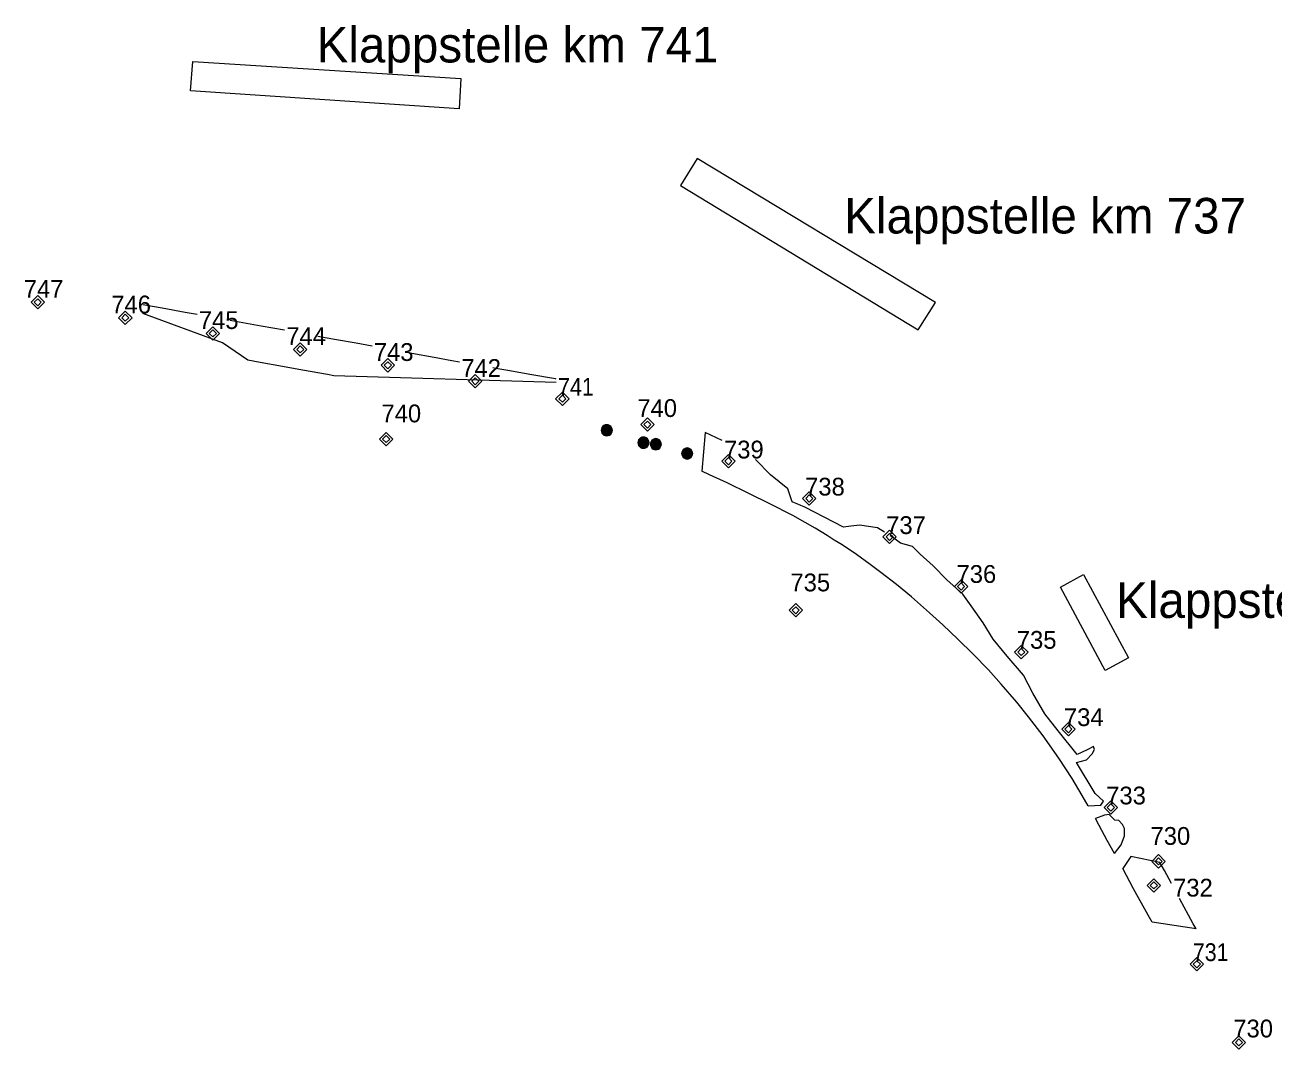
# Model space of a CAD drawing. Extents: x 3461750 to 3585707, y 5917729 to 5985917.
# Drawn here: x 3466140 to 3480178, y 5974405 to 5985917 of the extents above; entities that cross this region are included whole.
import ezdxf

# ---------------------------------------------------------------- set-up
doc = ezdxf.new("R2010")
doc.units = 0
doc.header["$LTSCALE"] = 80
doc.layers.add('11', color=7, linetype='Continuous')
for name, color, linetype, lineweight in [('12', 7, 'Continuous', 13), ('13', 7, 'Continuous', 13), ('14', 7, 'Continuous', 13), ('15', 7, 'Continuous', 13), ('2', 7, 'Continuous', 13), ('3', 7, 'Continuous', 13), ('6', 7, 'Continuous', 13)]:
    doc.layers.add(name, color=color, linetype=linetype, lineweight=lineweight)

msp = doc.modelspace()

# ---------------------------------------------------------------- hatches: boundary and pattern name
at = {"layer": '3'}
for points in [[(3472747.11, 5981360.51), (3472744.18, 5981377.13), (3472737.93, 5981392.23), (3472727.99, 5981405.19), (3472715.03, 5981415.13), (3472699.94, 5981421.38), (3472683.74, 5981423.51), (3472667.54, 5981421.38), (3472652.45, 5981415.13), (3472639.49, 5981405.19), (3472629.55, 5981392.23), (3472623.3, 5981377.13), (3472621.16, 5981360.94), (3472623.3, 5981344.74), (3472629.55, 5981329.65), (3472639.49, 5981316.69), (3472652.45, 5981306.75), (3472667.54, 5981300.5), (3472683.74, 5981298.36), (3472699.94, 5981300.5), (3472715.03, 5981306.75), (3472727.99, 5981316.69), (3472737.93, 5981329.65), (3472744.18, 5981344.74)], [(3473159.71, 5981220.86), (3473156.78, 5981237.48), (3473150.53, 5981252.58), (3473140.59, 5981265.54), (3473127.63, 5981275.48), (3473112.53, 5981281.73), (3473096.34, 5981283.86), (3473080.14, 5981281.73), (3473065.05, 5981275.48), (3473052.09, 5981265.54), (3473042.15, 5981252.58), (3473035.9, 5981237.48), (3473033.76, 5981221.29), (3473035.9, 5981205.09), (3473042.15, 5981190), (3473052.09, 5981177.04), (3473065.05, 5981167.1), (3473080.14, 5981160.85), (3473096.34, 5981158.71), (3473112.53, 5981160.85), (3473127.63, 5981167.1), (3473140.59, 5981177.04), (3473150.53, 5981190), (3473156.78, 5981205.09)], [(3473299.21, 5981203.67), (3473296.28, 5981220.3), (3473290.03, 5981235.39), (3473280.09, 5981248.35), (3473267.13, 5981258.29), (3473252.04, 5981264.54), (3473235.84, 5981266.68), (3473219.64, 5981264.54), (3473204.55, 5981258.29), (3473191.59, 5981248.35), (3473181.65, 5981235.39), (3473175.4, 5981220.3), (3473173.26, 5981204.1), (3473175.4, 5981187.91), (3473181.65, 5981172.81), (3473191.59, 5981159.85), (3473204.55, 5981149.91), (3473219.64, 5981143.66), (3473235.84, 5981141.53), (3473252.04, 5981143.66), (3473267.13, 5981149.91), (3473280.09, 5981159.85), (3473290.03, 5981172.81), (3473296.28, 5981187.91)], [(3473651.56, 5981099.08), (3473648.63, 5981115.71), (3473642.38, 5981130.8), (3473632.43, 5981143.76), (3473619.47, 5981153.7), (3473604.38, 5981159.95), (3473588.18, 5981162.09), (3473571.99, 5981159.95), (3473556.9, 5981153.7), (3473543.94, 5981143.76), (3473533.99, 5981130.8), (3473527.74, 5981115.71), (3473525.61, 5981099.51), (3473527.74, 5981083.32), (3473533.99, 5981068.22), (3473543.94, 5981055.26), (3473556.9, 5981045.32), (3473571.99, 5981039.07), (3473588.18, 5981036.94), (3473604.38, 5981039.07), (3473619.47, 5981045.32), (3473632.43, 5981055.26), (3473642.38, 5981068.22), (3473648.63, 5981083.32)]]:
    msp.add_hatch(color=256, dxfattribs=at).paths.add_polyline_path(points)

# ---------------------------------------------------------------- linework, layer by layer
at = {"layer": '12'}
for points in [[(3474810.19, 5979412.02), (3474735.1, 5979336.93), (3474810.19, 5979261.84), (3474885.28, 5979336.93)], [(3474810.19, 5979376.62), (3474770.5, 5979336.93), (3474810.19, 5979297.23), (3474849.88, 5979336.93)]]:
    msp.add_lwpolyline(points, close=True, dxfattribs=at)
at = {"layer": '13'}
for points in [[(3470202.57, 5981336.33), (3470127.48, 5981261.24), (3470202.57, 5981186.15), (3470277.66, 5981261.24)], [(3470202.57, 5981300.94), (3470162.88, 5981261.24), (3470202.57, 5981221.55), (3470242.26, 5981261.24)], [(3478889.97, 5976589.65), (3478814.88, 5976514.56), (3478889.97, 5976439.47), (3478965.06, 5976514.56)], [(3478889.97, 5976554.26), (3478850.28, 5976514.56), (3478889.97, 5976474.87), (3478929.67, 5976514.56)]]:
    msp.add_lwpolyline(points, close=True, dxfattribs=at)
at = {"layer": '14'}
for points in [[(3473140.85, 5981498.93), (3473065.76, 5981423.84), (3473140.85, 5981348.75), (3473215.94, 5981423.84)], [(3473140.85, 5981463.53), (3473101.16, 5981423.84), (3473140.85, 5981384.15), (3473180.55, 5981423.84)], [(3479794.56, 5974554.69), (3479719.47, 5974479.6), (3479794.56, 5974404.51), (3479869.65, 5974479.6)], [(3479794.56, 5974519.29), (3479754.87, 5974479.6), (3479794.56, 5974439.91), (3479834.26, 5974479.6)]]:
    msp.add_lwpolyline(points, close=True, dxfattribs=at)
at = {"layer": '15'}
for points in [[(3466284.6, 5982875.49), (3466209.51, 5982800.4), (3466284.6, 5982725.31), (3466359.69, 5982800.4)], [(3466284.6, 5982840.1), (3466244.91, 5982800.4), (3466284.6, 5982760.71), (3466324.3, 5982800.4)], [(3467269.12, 5982700.3), (3467194.03, 5982625.21), (3467269.12, 5982550.12), (3467344.21, 5982625.21)], [(3467269.12, 5982664.9), (3467229.43, 5982625.21), (3467269.12, 5982585.52), (3467308.82, 5982625.21)], [(3468253.65, 5982525.01), (3468178.56, 5982449.92), (3468253.65, 5982374.82), (3468328.74, 5982449.92)], [(3468253.65, 5982489.61), (3468213.95, 5982449.92), (3468253.65, 5982410.22), (3468293.34, 5982449.92)], [(3469237.29, 5982344.93), (3469162.2, 5982269.84), (3469237.29, 5982194.75), (3469312.38, 5982269.84)], [(3469237.29, 5982309.53), (3469197.6, 5982269.84), (3469237.29, 5982230.14), (3469276.98, 5982269.84)], [(3470221.62, 5982165.83), (3470146.52, 5982090.74), (3470221.62, 5982015.64), (3470296.71, 5982090.74)], [(3470221.62, 5982130.43), (3470181.92, 5982090.74), (3470221.62, 5982051.04), (3470261.31, 5982090.74)], [(3471204.87, 5981986.53), (3471129.78, 5981911.44), (3471204.87, 5981836.35), (3471279.96, 5981911.44)], [(3471204.87, 5981951.13), (3471165.17, 5981911.44), (3471204.87, 5981871.75), (3471244.56, 5981911.44)], [(3472184.36, 5981790.83), (3472109.27, 5981715.74), (3472184.36, 5981640.64), (3472259.45, 5981715.74)], [(3472184.36, 5981755.43), (3472144.67, 5981715.74), (3472184.36, 5981676.04), (3472224.05, 5981715.74)], [(3474051.6, 5981088.58), (3473976.5, 5981013.49), (3474051.6, 5980938.4), (3474126.69, 5981013.49)], [(3474051.6, 5981053.18), (3474011.9, 5981013.49), (3474051.6, 5980973.8), (3474091.29, 5981013.49)], [(3474961.02, 5980668.46), (3474885.93, 5980593.37), (3474961.02, 5980518.28), (3475036.11, 5980593.37)], [(3474961.02, 5980633.06), (3474921.33, 5980593.37), (3474961.02, 5980553.68), (3475000.71, 5980593.37)], [(3475865.41, 5980236.04), (3475790.32, 5980160.95), (3475865.41, 5980085.86), (3475940.5, 5980160.95)], [(3475865.41, 5980200.64), (3475825.72, 5980160.95), (3475865.41, 5980121.26), (3475905.11, 5980160.95)], [(3476668.78, 5979679.4), (3476593.69, 5979604.31), (3476668.78, 5979529.22), (3476743.87, 5979604.31)], [(3476668.78, 5979644), (3476629.09, 5979604.31), (3476668.78, 5979564.62), (3476708.48, 5979604.31)], [(3477346.76, 5978941.8), (3477271.67, 5978866.71), (3477346.76, 5978791.62), (3477421.85, 5978866.71)], [(3477346.76, 5978906.4), (3477307.07, 5978866.71), (3477346.76, 5978827.02), (3477386.45, 5978866.71)], [(3477876.25, 5978075.49), (3477801.16, 5978000.4), (3477876.25, 5977925.31), (3477951.34, 5978000.4)], [(3477876.25, 5978040.1), (3477836.56, 5978000.4), (3477876.25, 5977960.71), (3477915.95, 5978000.4)], [(3478353.16, 5977194.93), (3478278.07, 5977119.84), (3478353.16, 5977044.75), (3478428.25, 5977119.84)], [(3478353.16, 5977159.53), (3478313.47, 5977119.84), (3478353.16, 5977080.14), (3478392.85, 5977119.84)], [(3478836.9, 5976319.63), (3478761.81, 5976244.54), (3478836.9, 5976169.45), (3478911.99, 5976244.54)], [(3478836.9, 5976284.24), (3478797.21, 5976244.54), (3478836.9, 5976204.85), (3478876.59, 5976244.54)], [(3479320.44, 5975432.72), (3479245.35, 5975357.63), (3479320.44, 5975282.54), (3479395.53, 5975357.63)], [(3479320.44, 5975397.32), (3479280.75, 5975357.63), (3479320.44, 5975317.94), (3479360.14, 5975357.63)]]:
    msp.add_lwpolyline(points, close=True, dxfattribs=at)
at = {"layer": '2'}
for p, q in [((3472116.3, 5981895.86), (3469613.57, 5981973.34)), ((3471435.55, 5982055.47), (3471401.5, 5982061.18)), ((3473792.63, 5981336.72), (3473753.03, 5980900.59)), ((3473983, 5981244.62), (3473792.63, 5981336.72)), ((3479313.82, 5975754.3), (3478817.09, 5975830.57))]:
    msp.add_line(p, q, dxfattribs=at)
for points in [[(3468075.9, 5982662.03), (3467942.87, 5982686.13), (3467684.13, 5982731.93), (3467464.8, 5982772.48)], [(3468646.39, 5982148.83), (3468363.13, 5982345.41), (3467464.8, 5982674.94)], [(3469059.5, 5982484.49), (3468798.19, 5982531.25), (3468508.84, 5982584.67), (3468449.5, 5982595.18)], [(3470043.9, 5982306.23), (3469864.21, 5982339.06), (3469642.53, 5982379), (3469433.1, 5982416.12)], [(3471027.9, 5982126.11), (3470942.63, 5982142.19), (3470742.72, 5982180.08), (3470490.92, 5982224.9), (3470417.5, 5982238.38)], [(3469613.57, 5981973.34), (3469541.89, 5981986.43), (3469263.67, 5982035.84), (3469038.43, 5982077.15), (3468786.38, 5982122.36), (3468646.39, 5982148.83)], [(3472116.3, 5981934.82), (3472106.01, 5981937.11), (3471819.43, 5981988.67), (3471594.73, 5982027.05), (3471435.55, 5982055.47)], [(3475348.19, 5980270.21), (3474913.43, 5980496.97), (3474768.8, 5980557.91), (3474719.82, 5980700.78), (3474525.2, 5980860.16), (3474356.6, 5981030.39)], [(3474915.97, 5980325.59), (3474775, 5980401.07), (3474519.48, 5980533.69), (3474282.81, 5980648.54), (3474038.53, 5980768.46), (3473840.04, 5980861.23), (3473753.03, 5980900.59)], [(3475243.51, 5980126.46), (3475164.6, 5980176.95), (3475029.64, 5980259.47), (3474915.97, 5980325.59)], [(3475806.9, 5980213.81), (3475728.61, 5980262.6), (3475603.03, 5980282.52), (3475531.25, 5980294.92), (3475428.22, 5980281.84), (3475348.19, 5980270.21)], [(3478099.32, 5977137.79), (3478032.86, 5977256.15), (3477917.92, 5977445.61), (3477769.09, 5977673.14), (3477593.46, 5977925.78), (3477428.91, 5978140.43), (3477297.71, 5978304.59), (3477121.78, 5978507.13), (3476975.88, 5978667.48), (3476805.47, 5978843.55), (3476632.03, 5979012.89), (3476463.18, 5979172.36), (3476312.79, 5979310.06), (3476112.4, 5979486.33), (3475944.04, 5979625.88), (3475768.41, 5979761.72), (3475648.34, 5979850.78), (3475491.31, 5979964.26), (3475330.13, 5980071), (3475243.51, 5980126.46)], [(3478099.32, 5977137.79), (3478242.63, 5977147.17), (3478269.58, 5977192.58), (3478175.44, 5977275.59), (3477965.97, 5977627.34), (3478078.37, 5977654.49), (3478144.04, 5977723.05), (3478171.24, 5977773.14), (3478157.81, 5977806.15), (3478086.23, 5977769.53), (3477974.41, 5977715.23), (3477762.11, 5977983.01), (3477612.06, 5978172.27), (3477477.39, 5978406.74), (3477372.61, 5978607.52), (3477187.7, 5978821.48), (3477030.76, 5979013.18), (3476917.53, 5979195.51), (3476781.35, 5979385.16), (3476688.77, 5979518.16), (3476510.06, 5979678.81), (3476353.61, 5979835.35), (3476210.16, 5979966.31), (3476123.88, 5980055.27), (3475987.89, 5980093.07), (3475896.14, 5980158.2), (3475870.47, 5980174.2)], [(3478394.97, 5976601.17), (3478471.19, 5976699.71), (3478506.98, 5976802.64), (3478505.37, 5976882.23), (3478485.06, 5976928.12), (3478442.68, 5976974.32), (3478398.49, 5976976.95), (3478333.98, 5977040.33), (3478283.2, 5977034.57), (3478179.15, 5976995.61)], [(3478394.97, 5976601.17), (3478313.62, 5976748.54), (3478223.29, 5976917.09), (3478179.15, 5976995.61)], [(3478906.01, 5976501.86), (3478578.81, 5976567.48), (3478487.11, 5976432.81)], [(3479034, 5976266.9), (3478955.62, 5976411.43), (3478906.01, 5976501.86)], [(3478817.09, 5975830.57), (3478772.9, 5975910.64), (3478610.06, 5976206.35), (3478487.11, 5976432.81)], [(3479313.82, 5975754.3), (3479281.1, 5975813.18), (3479125.34, 5976098.5)]]:
    msp.add_lwpolyline(points, dxfattribs=at)
at = {"layer": '3'}
for points in [[(3472747.11, 5981360.51), (3472744.18, 5981377.13), (3472737.93, 5981392.23), (3472727.99, 5981405.19), (3472715.03, 5981415.13), (3472699.94, 5981421.38), (3472683.74, 5981423.51), (3472667.54, 5981421.38), (3472652.45, 5981415.13), (3472639.49, 5981405.19), (3472629.55, 5981392.23), (3472623.3, 5981377.13), (3472621.16, 5981360.94), (3472623.3, 5981344.74), (3472629.55, 5981329.65), (3472639.49, 5981316.69), (3472652.45, 5981306.75), (3472667.54, 5981300.5), (3472683.74, 5981298.36), (3472699.94, 5981300.5), (3472715.03, 5981306.75), (3472727.99, 5981316.69), (3472737.93, 5981329.65), (3472744.18, 5981344.74)], [(3473159.71, 5981220.86), (3473156.78, 5981237.48), (3473150.53, 5981252.58), (3473140.59, 5981265.54), (3473127.63, 5981275.48), (3473112.53, 5981281.73), (3473096.34, 5981283.86), (3473080.14, 5981281.73), (3473065.05, 5981275.48), (3473052.09, 5981265.54), (3473042.15, 5981252.58), (3473035.9, 5981237.48), (3473033.76, 5981221.29), (3473035.9, 5981205.09), (3473042.15, 5981190), (3473052.09, 5981177.04), (3473065.05, 5981167.1), (3473080.14, 5981160.85), (3473096.34, 5981158.71), (3473112.53, 5981160.85), (3473127.63, 5981167.1), (3473140.59, 5981177.04), (3473150.53, 5981190), (3473156.78, 5981205.09)], [(3473299.21, 5981203.67), (3473296.28, 5981220.3), (3473290.03, 5981235.39), (3473280.09, 5981248.35), (3473267.13, 5981258.29), (3473252.04, 5981264.54), (3473235.84, 5981266.68), (3473219.64, 5981264.54), (3473204.55, 5981258.29), (3473191.59, 5981248.35), (3473181.65, 5981235.39), (3473175.4, 5981220.3), (3473173.26, 5981204.1), (3473175.4, 5981187.91), (3473181.65, 5981172.81), (3473191.59, 5981159.85), (3473204.55, 5981149.91), (3473219.64, 5981143.66), (3473235.84, 5981141.53), (3473252.04, 5981143.66), (3473267.13, 5981149.91), (3473280.09, 5981159.85), (3473290.03, 5981172.81), (3473296.28, 5981187.91)], [(3473651.56, 5981099.08), (3473648.63, 5981115.71), (3473642.38, 5981130.8), (3473632.43, 5981143.76), (3473619.47, 5981153.7), (3473604.38, 5981159.95), (3473588.18, 5981162.09), (3473571.99, 5981159.95), (3473556.9, 5981153.7), (3473543.94, 5981143.76), (3473533.99, 5981130.8), (3473527.74, 5981115.71), (3473525.61, 5981099.51), (3473527.74, 5981083.32), (3473533.99, 5981068.22), (3473543.94, 5981055.26), (3473556.9, 5981045.32), (3473571.99, 5981039.07), (3473588.18, 5981036.94), (3473604.38, 5981039.07), (3473619.47, 5981045.32), (3473632.43, 5981055.26), (3473642.38, 5981068.22), (3473648.63, 5981083.32)]]:
    msp.add_lwpolyline(points, close=True, dxfattribs=at)
at = {"layer": '6'}
for points in [[(3468027, 5985506.93), (3471043.07, 5985317.09), (3471022.66, 5984973.54), (3468003.17, 5985175.1)], [(3473699.71, 5984414.16), (3473511.96, 5984112.11), (3476185.01, 5982489.26), (3476380.18, 5982796.48)], [(3478291.26, 5978658.89), (3477785.99, 5979595.41), (3478047.07, 5979740.82), (3478553.86, 5978803.42)]]:
    msp.add_lwpolyline(points, close=True, dxfattribs=at)

# ---------------------------------------------------------------- texts
at = {"layer": '11'}
for s, p in [('Klappstelle km 741 ', (3469421.1, 5985495.8)), ('Klappstelle km 737 ', (3475354.5, 5983572.9)), ('Klappstelle km 733 ', (3478412.8, 5979251))]:
    msp.add_text(s, height=400, dxfattribs=at).set_placement(p)
at = {"layer": '12'}
msp.add_text('735', height=200, dxfattribs=at).set_placement((3474750, 5979550))
at = {"layer": '13'}
for s, p in [('740', (3470150, 5981450)), ('730', (3478800, 5976700))]:
    msp.add_text(s, height=200, dxfattribs=at).set_placement(p)
at = {"layer": '14'}
for s, p in [('740', (3473027.9, 5981510.2)), ('730', (3479731, 5974535))]:
    msp.add_text(s, height=200, dxfattribs=at).set_placement(p)
at = {"layer": '15'}
for s, p in [('747', (3466126.6, 5982849.8)), ('746', (3467111.2, 5982674.6)), ('745', (3468095.9, 5982499.3)), ('744', (3469079.5, 5982319.1)), ('743', (3470063.9, 5982140.1)), ('742', (3471047.9, 5981960.6)), ('739', (3474003, 5981043.8)), ('738', (3474914.9, 5980626.9)), ('737', (3475826.9, 5980194.2)), ('736', (3476617.9, 5979644.8)), ('735', (3477296, 5978904.4)), ('734', (3477826, 5978035.4)), ('733', (3478301.5, 5977154.6)), ('732', (3479054, 5976118.5))]:
    msp.add_text(s, height=200, dxfattribs=at).set_placement(p)
at = {"layer": '15', "width": 0.9}
for s, p in [('741', (3472136.3, 5981749.2)), ('731', (3479275.7, 5975393.1))]:
    msp.add_text(s, height=200, dxfattribs=at).set_placement(p)

doc.saveas('drawing.dxf')
